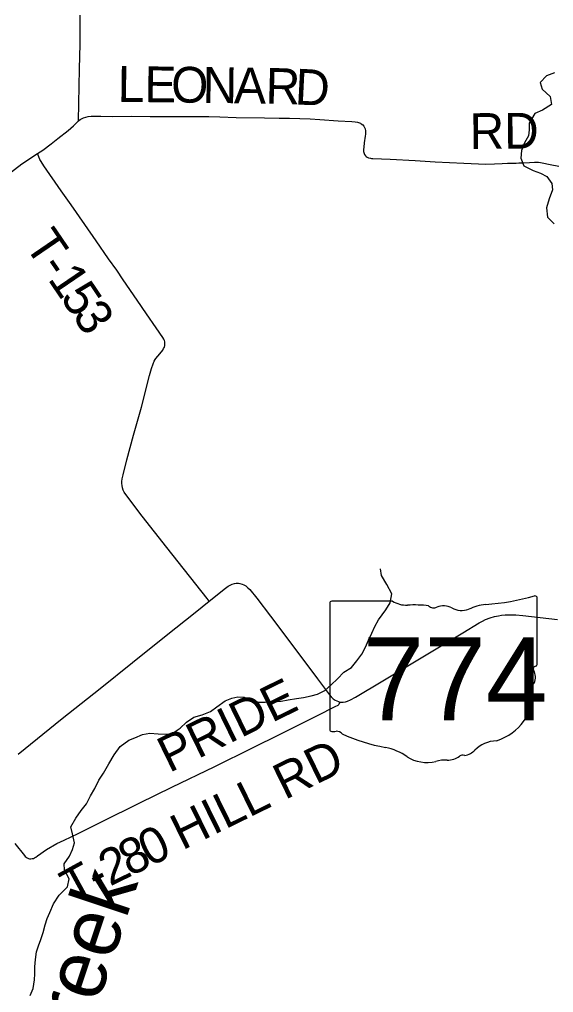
# Model space of a CAD drawing. Extents: x 1451455 to 1749751, y 218250 to 574981.
# Drawn here: x 1535486 to 1539967, y 333315 to 341475 of the extents above; entities that cross this region are included whole.
import ezdxf

# ---------------------------------------------------------------- set-up
doc = ezdxf.new("R2010")
doc.units = 0
for name, color, linetype in [('GM_X_Minor_River', 7, 'Continuous'), ('GM_X_Minor_River_Text', 7, 'Continuous'), ('GM_X_State_Location', 7, 'Continuous'), ('GM_X_State_Route', 7, 'Continuous'), ('GM_X_State_Shield', 7, 'Continuous'), ('GM_X_Township_Road', 7, 'Continuous'), ('GM_X_Township_Road_Text', 7, 'Continuous')]:
    doc.layers.add(name, color=color, linetype=linetype)

msp = doc.modelspace()

# ---------------------------------------------------------------- linework, layer by layer
at = {"layer": 'GM_X_Minor_River'}
for points in [[(1539975.3, 341027.8), (1539906.7, 341002.9), (1539853.6, 340945.7), (1539872.7, 340889.2), (1539939.7, 340827.9), (1539950.6, 340761.5), (1539873.6, 340714.7), (1539809, 340685.7), (1539761.5, 340604.3), (1539762.5, 340548.1), (1539755.6, 340498.1), (1539724.5, 340440.5), (1539699.3, 340374.7), (1539692.2, 340312.7), (1539717.1, 340246.1), (1539796.6, 340208.6), (1539858.3, 340185.5), (1539910, 340158.5), (1539953, 340099.6), (1539958.1, 340047.4), (1539930.8, 339971.6), (1539907.4, 339895.8), (1539916, 339817.4), (1539971.1, 339760.3)], [(1536835.2, 335530.9), (1536886.2, 335582.2), (1536949, 335625.2), (1537019.5, 335644.1), (1537088.2, 335673), (1537143, 335712.2), (1537211.9, 335761.2), (1537268.5, 335784.3), (1537318.8, 335795.5), (1537370.8, 335790.6), (1537428.5, 335767.5), (1537488.3, 335750.4), (1537546.4, 335749.4), (1537614.6, 335752.2), (1537680.8, 335759.1), (1537739.1, 335768.2), (1537811.5, 335781), (1537869.8, 335790), (1537932.1, 335803), (1537986.5, 335818.1), (1538047.1, 335847.1), (1538102, 335894.3), (1538155, 335945.6), (1538208.1, 336000.9), (1538270.9, 336041.9), (1538316, 336095.3), (1538359, 336152.8), (1538388.1, 336210.5), (1538413.2, 336270.2), (1538442.3, 336327.9), (1538467.3, 336383.7), (1538498.3, 336441.3), (1538559.9, 336524.5), (1538595, 336582.1), (1538610.3, 336658.1), (1538567.6, 336737.1), (1538524.8, 336812), (1538515.8, 336868.4)], [(1535575.7, 333291.1), (1535600.8, 333348.9), (1535612, 333421), (1535614.9, 333471.1), (1535616, 333531.3), (1535619, 333591.4), (1535628.1, 333655.5), (1535645.1, 333707.3), (1535666, 333759.1), (1535685.1, 333819), (1535700.3, 333883), (1535717.2, 333934.9), (1535740.1, 333986.6), (1535771.4, 334058.3), (1535818.8, 334131.8), (1535890.2, 334202.8), (1535903.4, 334268.8), (1535864.6, 334343.7), (1535859.5, 334393.9), (1535904.6, 334457.4), (1535929.7, 334515.1), (1535946.7, 334571), (1535932, 334645.5), (1535917, 334706), (1535958.3, 334777.5), (1536003.6, 334842.9), (1536048.6, 334898.3), (1536081.8, 334964), (1536117, 335025.6), (1536152.2, 335095.2), (1536191.4, 335154.7), (1536234.8, 335232.2), (1536280.2, 335309.7), (1536329.5, 335379.1), (1536402.6, 335432), (1536453, 335451.2), (1536517.7, 335480.2), (1536580, 335491.1), (1536650, 335483.9), (1536712.1, 335482.9), (1536768.3, 335487.9), (1536835.2, 335530.9)]]:
    msp.add_lwpolyline(points, dxfattribs=at)
at = {"layer": 'GM_X_State_Route'}
msp.add_lwpolyline([(1535473.8, 335314.8), (1535844.8, 335612.5), (1536163.3, 335865.7), (1536434.9, 336082.8), (1536716.2, 336308.8), (1536959.9, 336503.2), (1537077.5, 336597.7), (1537213.4, 336706.8), (1537238, 336724), (1537252.7, 336732.1), (1537271.3, 336740.1), (1537291.1, 336745.5), (1537304.4, 336747.5), (1537324.9, 336747.3), (1537335, 336745.9), (1537354.6, 336740.1), (1537367, 336734.6), (1537384.7, 336724.3), (1537403.1, 336709.7), (1537419.8, 336693.4), (1537478.5, 336621.8), (1537590.8, 336472.1), (1537804.4, 336189.4), (1537987, 335944.9), (1538087.6, 335811.6), (1538102.4, 335794.5), (1538118.9, 335779.3), (1538134.3, 335768), (1538147.9, 335760.2), (1538162.5, 335754.2), (1538176.2, 335751), (1538190, 335749.6), (1538202.5, 335750), (1538221.1, 335753.2), (1538239.3, 335759), (1538262.9, 335769.4), (1538306.2, 335792.2), (1538534.5, 335928), (1538953.4, 336179.9), (1539206.8, 336331.3), (1539344.2, 336415.2), (1539371.5, 336430.4), (1539397.4, 336442), (1539434.6, 336456.1), (1539471.5, 336467.6), (1539505, 336474.5), (1539531.2, 336478.7), (1539560.9, 336481.5), (1539603.8, 336483), (1539650, 336482), (1539709.1, 336477), (1539999.2, 336443.7)], dxfattribs=at)
at = {"layer": 'GM_X_State_Shield'}
for p, q in [((1538616.8, 336596.7), (1538107.1, 336596.7)), ((1539830.2, 336070.1), (1539830.2, 336622.9)), ((1538090, 336578.5), (1538090, 335521.9)), ((1539830, 336070.3), (1539830.2, 336070.1))]:
    msp.add_line(p, q, dxfattribs=at)
for centre, major_axis, start_param, end_param in [((1538109.9, 336580.8), (20.2, 0), 1.712693, 3.28349), ((1538738.1, 336719.4), (195.5, 0), 4.042523, 4.731795), ((1539210.3, 338037.2), (1845.5, 0), 4.814394, 5.042369), ((1539810.9, 336625.2), (19.4, 0), 6.141152, 7.989035), ((1538803, 336003.5), (702, 0), 1.404758, 1.657858), ((1538962.3, 336586.2), (56.4, 0), 3.836095, 5.185415), ((1539045.2, 336464.1), (117.3, 0), 0.950623, 2.079405), ((1539196.5, 336631.6), (141.1, 0), 4.081561, 5.145723), ((1539445.7, 336274), (371.3, 0), 1.699011, 2.107814), ((1539825.7, 336029.6), (30, 0), 1.883978, 3.671073), ((1539635, 335959.7), (180, 0), 5.934695, 6.695948), ((1539809.5, 336068), (20.7, 0), 5.05454, 6.418171), ((1539899.6, 335838.8), (130.9, 0), 2.387724, 3.262537), ((1539313.7, 335768.5), (461.6, 0), 5.101752, 6.440018), ((1538110.1, 335519.6), (20.3, 0), 3.00124, 4.508301), ((1538113.2, 335627.7), (155.2, 0), 4.665946, 4.897461), ((1538145, 335460.9), (56, 0), 0.519207, 1.627899), ((1538851.6, 336410.3), (1332.7, 0), 4.195997, 4.488961), ((1538454.2, 335047.2), (417, 0), 0.823519, 1.323587), ((1539508.3, 335225.2), (252.8, 0), 1.647645, 2.488434), ((1538905.2, 335455.7), (264.6, 0), 4.026481, 4.996735), ((1539077.4, 335376.5), (141, 0), 4.691044, 5.507374), ((1539205, 335274.2), (39.7, 0), 1.147584, 2.315152), ((1539188, 335419.5), (149.1, 0), 4.937069, 5.64225), ((1539058.1, 335090.3), (217.4, 0), 1.495662, 1.94098)]:
    msp.add_ellipse(centre, major_axis=major_axis, ratio=0.8, start_param=start_param, end_param=end_param, dxfattribs=at)
at = {"layer": 'GM_X_Township_Road'}
for points in [[(1535981, 340623.9), (1535989.8, 341061.6), (1535993.8, 341268.3), (1535995.9, 341511.1)], [(1535638.2, 340351.8), (1535681.2, 340378.9), (1535751.7, 340432.9), (1535808.8, 340476.9), (1535893.9, 340543.9), (1535938.9, 340582.1), (1535981, 340623.9)], [(1535981, 340623.9), (1535995.8, 340635.8), (1536011, 340644.5), (1536024, 340650.1), (1536041.8, 340655.4), (1536063.3, 340660.2), (1536086.5, 340662.7), (1536115.5, 340664.4), (1536168, 340663.2), (1536266.4, 340661.8), (1536423.5, 340662.6), (1536583.8, 340661.3), (1536711.7, 340660.2), (1536833, 340660.5), (1536944.5, 340661.7), (1537075.7, 340660.5), (1537167.4, 340657.4), (1537305.1, 340653.9), (1537541.2, 340650.9), (1537665.7, 340648.4), (1537750.9, 340647.5), (1537839.3, 340645.4), (1537924.5, 340641.2), (1538006.3, 340635.7), (1538160.1, 340625.3), (1538275, 340618.9), (1538301.6, 340616.8), (1538320.9, 340613.3), (1538329.6, 340611.3), (1538339.1, 340608), (1538347.2, 340604.4), (1538353.9, 340600.5), (1538366, 340591.1), (1538374.3, 340581.1), (1538381.7, 340568.5), (1538385.9, 340556.9), (1538388.8, 340541), (1538389.8, 340524.6), (1538389, 340511.7), (1538387.3, 340496.9), (1538378.8, 340439.7), (1538374.1, 340404.8), (1538372.5, 340384.3), (1538373.1, 340376.4), (1538373.3, 340367.9), (1538374.9, 340358.7), (1538376.8, 340351.7), (1538381.7, 340341.5), (1538388, 340332.3), (1538394.2, 340326.4), (1538402.3, 340320.4), (1538415.4, 340314.8), (1538430.3, 340310.7), (1538440.6, 340309.6), (1538450.7, 340308.5), (1538523, 340306.7), (1538595.1, 340303.6), (1538804.7, 340292.4), (1538975, 340282.1), (1539214.1, 340270.6), (1539397.5, 340261.7), (1539472.8, 340263.2), (1539534.8, 340266.8), (1539580.6, 340268.6), (1539613.4, 340269.5), (1539652.7, 340270.3), (1539675.7, 340271.3), (1539708.4, 340272.7), (1539764.1, 340276.6), (1539806.6, 340278.5), (1539824.8, 340277.8), (1539839.4, 340277.1), (1539857.3, 340275.2), (1539871.9, 340272.8), (1539939.4, 340259.2), (1540010.1, 340245.1)], [(1533834.5, 339284.3), (1533955, 339271.8), (1534078.6, 339254.5), (1534130.7, 339248.5), (1534166.8, 339247.3), (1534186.4, 339248.6), (1534212.2, 339252.1), (1534243.6, 339261.6), (1534261.4, 339270.2), (1534281.3, 339281.1), (1534305.4, 339298.2), (1534336.3, 339322.6), (1534371.6, 339352.1), (1534429.6, 339400.4), (1534649.1, 339582.9), (1534795, 339699.7), (1535131.2, 339967.4), (1535358.8, 340150.2), (1535506.1, 340262.9), (1535638.2, 340351.8)], [(1537077.5, 336597.7), (1537060.2, 336619.5), (1536722.6, 337046.6), (1536514.6, 337308.8), (1536377, 337492.1), (1536365.1, 337511.8), (1536357, 337529), (1536350.5, 337548.5), (1536347.2, 337566.1), (1536345.9, 337583.9), (1536346.1, 337600.3), (1536348.8, 337623.1), (1536354.9, 337655.4), (1536386.1, 337782.9), (1536442.8, 337988.5), (1536510.2, 338225.1), (1536577.4, 338488.4), (1536594.4, 338548.4), (1536606.5, 338585.9), (1536616.6, 338610.1), (1536624.4, 338624.4), (1536630, 338632.4), (1536664, 338671.7), (1536687.7, 338702.4), (1536695.5, 338715.3), (1536701.4, 338728.2), (1536705.1, 338740.4), (1536706.7, 338757.1), (1536705.7, 338770.2), (1536702, 338783.4), (1536697.6, 338795.1), (1536689.4, 338809.2), (1536632.5, 338889.5), (1536552.3, 339005.4), (1536472.8, 339122), (1536355.8, 339292.4), (1536302.4, 339371.2), (1536233.1, 339466.9), (1536129.4, 339618.6), (1536034.3, 339756.3), (1535919.2, 339920.1), (1535834.8, 340037.2), (1535689.5, 340247.9), (1535668.1, 340282.5), (1535658.1, 340301.6), (1535649.3, 340322.8), (1535638.2, 340351.8)], [(1535447.1, 334564.8), (1535526.9, 334464.5), (1535534.4, 334456.9), (1535541.4, 334451.1), (1535550, 334444.8), (1535561, 334439.8), (1535570.4, 334437.4), (1535580.2, 334436.9), (1535593.2, 334438.2), (1535603, 334440.4), (1535611.2, 334443.9), (1535623, 334451.2), (1535636.6, 334460.4), (1535712.3, 334514.7), (1535798.6, 334564.7), (1535861.6, 334592.3), (1535979.6, 334649.8), (1536252.7, 334785.5), (1536417, 334867.1), (1536496.4, 334906.2), (1536765.1, 335036.3), (1537123.8, 335211.7), (1537440.6, 335367.5), (1537674.6, 335481.6), (1537757.9, 335523.8), (1537980.3, 335635), (1538141.6, 335715.7), (1538153.2, 335721.8), (1538159.1, 335726.2), (1538164.1, 335730.8), (1538168.6, 335737.1), (1538176.2, 335751)]]:
    msp.add_lwpolyline(points, dxfattribs=at)

# ---------------------------------------------------------------- texts
at = {"layer": 'GM_X_Minor_River_Text'}
msp.add_text('Creek', height=500.12, rotation=71.56677, dxfattribs=at).set_placement((1535921.2, 332548))
at = {"layer": 'GM_X_State_Location'}
for s in ['s', 'r']:
    msp.add_text(s, height=1, dxfattribs=at).set_placement((1538940.5, 335979.9))
msp.add_text('774', height=1, rotation=0.00001, dxfattribs=at).set_placement((1538587.5, 335907.2))
at = {"layer": 'GM_X_State_Shield'}
msp.add_text('774', height=696.1, dxfattribs=at).set_placement((1538364.1, 335596.4))
at = {"layer": 'GM_X_Township_Road_Text'}
for s, rotation, p in [('L', 359.29929, (1536308.5, 340784.5)), ('E', 359.29947, (1536532.9, 340781.8)), ('O', 359.30082, (1536757.3, 340779)), ('N', 359.30057, (1537021.3, 340775.8)), ('A', 359.27143, (1537285.2, 340772.6)), ('R', 358.5421, (1537548.2, 340769.3)), ('D', 357.09912, (1537792.5, 340763.1)), ('RD', 0.42374, (1539264, 340388.4)), ('T', 304.34619, (1535522.1, 339585.1)), ('-', 304.33526, (1535648.6, 339399.8)), ('1', 304.24936, (1535718.1, 339298.2)), ('5', 303.94915, (1535821.8, 339145.8)), ('3', 302.92799, (1535924.3, 338993.7)), ('PRIDE', 26.03475, (1536742, 335154.7)), ('HILL RD', 26.17272, (1536852.2, 334505.5)), ('0', 26.43669, (1536578.6, 334366.7)), ('8', 26.14032, (1536411.1, 334284.6)), ('2', 26.12518, (1536245.1, 334203.2)), ('T', 28.73325, (1535941, 334042.6)), ('-', 26.1985, (1536134.7, 334148.8))]:
    msp.add_text(s, height=300, rotation=rotation, dxfattribs=at).set_placement(p)

doc.saveas('drawing.dxf')
